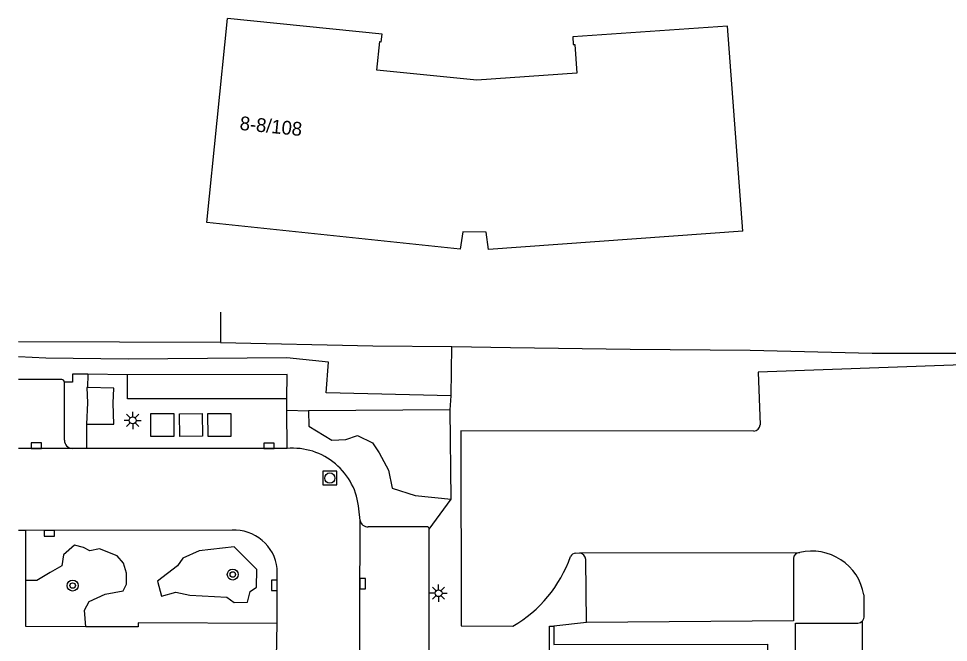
# Model space of a CAD drawing. Extents: x 132573 to 132944, y 398226 to 398676.
# Drawn here: x 132573 to 132640.6, y 398381.9 to 398427.3 of the extents above; entities that cross this region are included whole.
import ezdxf

# ---------------------------------------------------------------- set-up
doc = ezdxf.new("R2010")
doc.units = 0
for name, color, linetype in [('gg-afsc-hekwerk', 7, 'Continuous'), ('gg-anno-huisnummerreeks BGT', 7, 'Continuous'), ('gg-bbg-hoofdgebouw', 7, 'Continuous'), ('gg-bbg-lage trafo', 7, 'Continuous'), ('gg-knt-verharding', 7, 'Continuous'), ('gg-knt-verharding nz', 7, 'Continuous'), ('gg-kwrk-afval apart plaats', 7, 'Continuous'), ('gt-grn-groengrens', 7, 'Continuous'), ('gt-grn-vlakafsluiter', 7, 'Continuous'), ('gt-symb-boom', 7, 'Continuous'), ('gt-symb-kolk', 7, 'Continuous'), ('gt-symb-lichtmast', 7, 'Continuous'), ('gt-symb-rioolschacht', 7, 'Continuous')]:
    doc.layers.add(name, color=color, linetype=linetype)

msp = doc.modelspace()

# ---------------------------------------------------------------- linework, layer by layer
at = {"layer": 'gg-afsc-hekwerk'}
for p, q in [((132587.691, 398405.939), (132587.704, 398403.725)), ((132587.704, 398403.725), (132573.021, 398403.764))]:
    msp.add_line(p, q, dxfattribs=at)
for points in [[(132587.704, 398403.725), (132598.78, 398403.494), (132604.511, 398403.424)], [(132604.511, 398403.424), (132608.788, 398403.371), (132617.481, 398403.23), (132626.206, 398403.178), (132635.061, 398402.95), (132641.245, 398402.951), (132661.988, 398402.675), (132670.216, 398402.551), (132684.626, 398402.413)]]:
    msp.add_lwpolyline(points, dxfattribs=at)
at = {"layer": 'gg-bbg-hoofdgebouw'}
for p, q in [((132611.557, 398312.941), (132611.606, 398383.108)), ((132611.606, 398383.108), (132611.918, 398383.098))]:
    msp.add_line(p, q, dxfattribs=at)
for points in [[(132625.661, 398411.824), (132607.176, 398410.488), (132607.015, 398411.737), (132605.316, 398411.777), (132605.125, 398410.51), (132586.702, 398412.435), (132588.218, 398427.268)], [(132625.661, 398411.824), (132624.561, 398426.725), (132613.308, 398425.936), (132613.347, 398425.377), (132613.457, 398425.385), (132613.603, 398423.3), (132606.339, 398422.781), (132599.066, 398423.519), (132599.276, 398425.599), (132599.386, 398425.588), (132599.441, 398426.135), (132588.218, 398427.268)], [(132611.918, 398383.098), (132611.926, 398381.783), (132627.465, 398381.808), (132627.459, 398367.583), (132627.387, 398367.583), (132627.398, 398314.148)]]:
    msp.add_lwpolyline(points, dxfattribs=at)
at = {"layer": 'gg-bbg-lage trafo'}
for points in [[(132578.027, 398400.446), (132577.984, 398400.447), (132578.02, 398399.335), (132577.953, 398397.788)], [(132577.953, 398397.788), (132579.956, 398397.777), (132579.903, 398399.318), (132579.955, 398400.403), (132578.027, 398400.446)]]:
    msp.add_lwpolyline(points, dxfattribs=at)
at = {"layer": 'gg-knt-verharding'}
for p, q in [((132578.048, 398401.413), (132578.027, 398400.446)), ((132580.946, 398401.383), (132578.048, 398401.413)), ((132576.158, 398401.04), (132573.021, 398401.039)), ((132576.351, 398396.615), (132576.352, 398400.846)), ((132592.526, 398398.817), (132592.531, 398399.625)), ((132592.535, 398396.022), (132592.526, 398398.817)), ((132577.953, 398397.788), (132577.953, 398396.015)), ((132577.953, 398396.015), (132576.907, 398396.016)), ((132597.845, 398390.796), (132597.755, 398391.624)), ((132602.686, 398390.334), (132598.438, 398390.328)), ((132573.55, 398390.052), (132573.021, 398390.051)), ((132573.546, 398386.427), (132573.55, 398390.052)), ((132588.541, 398390.078), (132573.55, 398390.052)), ((132602.886, 398325.225), (132602.874, 398390.164)), ((132613.536, 398388.42), (132613.808, 398388.425)), ((132613.808, 398388.425), (132629.803, 398388.459)), ((132629.803, 398388.459), (132629.807, 398388.459)), ((132614.295, 398383.378), (132614.258, 398387.955)), ((132591.822, 398383.309), (132591.815, 398387.305)), ((132591.774, 398380.797), (132591.822, 398383.309)), ((132634.355, 398373.168), (132634.362, 398383.497))]:
    msp.add_line(p, q, dxfattribs=at)
for points in [[(132645.674, 398402.24), (132626.792, 398401.58), (132626.926, 398397.736)], [(132592.531, 398399.625), (132580.949, 398399.629), (132580.946, 398401.383)], [(132626.472, 398397.27), (132605.161, 398397.294), (132605.19, 398383.135), (132608.954, 398383.112)], [(132592.535, 398396.022), (132591.233, 398396.011), (132577.953, 398396.015)], [(132629.347, 398388.014), (132629.341, 398383.498), (132614.295, 398383.378)], [(132577.901, 398383.068), (132573.543, 398383.08), (132573.546, 398386.427)], [(132634.467, 398385.388), (132634.471, 398383.784), (132634.441, 398383.631), (132634.362, 398383.497)], [(132591.822, 398383.309), (132581.707, 398383.338), (132581.706, 398383.054), (132577.901, 398383.068)], [(132634.001, 398373.324), (132629.494, 398373.344), (132629.497, 398383.328), (132634.028, 398383.333), (132634.212, 398383.38), (132634.362, 398383.497)]]:
    msp.add_lwpolyline(points, dxfattribs=at)
for centre, radius, start, end in [((132576.144, 398400.832), 0.208, 3.75762, 86.24238), ((132626.422, 398397.772), 0.505, 275.63046, 355.86413), ((132576.956, 398396.619), 0.605, 180.39874, 265.33705), ((132592.948, 398391.215), 4.825, 49.8917, 94.90614), ((132592.949, 398391.216), 4.823, 4.8542, 49.89874), ((132598.417, 398390.911), 0.584, 191.39186, 272.04662), ((132602.695, 398390.155), 0.179, 2.88914, 92.8676), ((132588.705, 398386.952), 3.131, 49.74849, 93.00478), ((132588.706, 398386.953), 3.129, 6.45692, 49.73771), ((132613.554, 398387.95), 0.47, 92.18037, 153.74765), ((132613.743, 398387.913), 0.517, 4.71286, 82.79641), ((132629.806, 398388), 0.459, 90.40234, 178.19872), ((132630.694, 398384.735), 3.829, 9.82707, 103.40213), ((132604.284, 398391.232), 9.367, 299.90714, 340.84453)]:
    msp.add_arc(centre, radius, start, end, dxfattribs=at)
at = {"layer": 'gg-knt-verharding nz'}
for points in [[(132576.907, 398396.016), (132574.303, 398396.025), (132573.021, 398396.025)], [(132597.785, 398324.487), (132597.792, 398326.07), (132597.768, 398341.148), (132597.78, 398355.563), (132597.776, 398371.059), (132597.845, 398390.796)]]:
    msp.add_lwpolyline(points, dxfattribs=at)
at = {"layer": 'gg-kwrk-afval apart plaats'}
for points in [[(132584.309, 398396.896), (132582.639, 398396.884), (132582.633, 398398.553), (132584.303, 398398.565), (132584.309, 398396.896)], [(132586.37, 398398.565), (132586.381, 398396.907), (132584.73, 398396.89), (132584.719, 398398.548), (132586.37, 398398.565)], [(132588.448, 398398.553), (132588.456, 398396.901), (132586.794, 398396.903), (132586.786, 398398.555), (132588.448, 398398.553)]]:
    msp.add_lwpolyline(points, dxfattribs=at)
at = {"layer": 'gt-grn-groengrens'}
for p, q in [((132604.387, 398398.836), (132604.468, 398399.855)), ((132592.526, 398398.817), (132594.101, 398398.749)), ((132604.387, 398398.836), (132594.101, 398398.749)), ((132604.469, 398392.329), (132604.387, 398398.836))]:
    msp.add_line(p, q, dxfattribs=at)
for points in [[(132604.468, 398399.855), (132595.373, 398400.057), (132595.538, 398402.286), (132592.517, 398402.604), (132580.975, 398402.502), (132574.993, 398402.589), (132573.021, 398402.685)], [(132578.048, 398401.413), (132576.941, 398401.43), (132576.946, 398400.842), (132576.352, 398400.846)], [(132592.531, 398399.625), (132592.556, 398401.402), (132580.946, 398401.383)], [(132594.101, 398398.749), (132594.117, 398397.634), (132595.801, 398396.636), (132596.808, 398396.667), (132597.653, 398396.97), (132598.746, 398396.424), (132599.236, 398395.698), (132599.91, 398394.434), (132600.166, 398393.128), (132601.857, 398392.593), (132604.469, 398392.329)], [(132577.901, 398383.068), (132577.812, 398384.271), (132578.141, 398384.903), (132579.31, 398385.429), (132580.631, 398385.679), (132580.871, 398386.157), (132580.871, 398386.969), (132580.64, 398387.687), (132580.192, 398388.22), (132578.894, 398388.723), (132578.188, 398388.576), (132577.747, 398388.831), (132577.077, 398388.988), (132576.296, 398388.299), (132576.168, 398387.489), (132575.328, 398387.006), (132574.342, 398386.426), (132573.546, 398386.427)], [(132586.158, 398388.584), (132584.949, 398388.058), (132584.563, 398387.501), (132583.117, 398386.369), (132583.42, 398385.283), (132584.452, 398385.575), (132585.471, 398385.361), (132588.16, 398385.213), (132588.703, 398384.833), (132589.651, 398384.848), (132589.861, 398385.626), (132590.307, 398385.947), (132590.332, 398387.216), (132588.691, 398388.861), (132586.158, 398388.584)]]:
    msp.add_lwpolyline(points, dxfattribs=at)
at = {"layer": 'gt-grn-vlakafsluiter'}
for p, q in [((132604.468, 398399.855), (132604.511, 398403.424)), ((132602.874, 398390.164), (132604.469, 398392.329)), ((132614.295, 398383.378), (132611.918, 398383.098))]:
    msp.add_line(p, q, dxfattribs=at)
at = {"layer": 'gt-symb-boom'}
for centre, radius in [((132588.589, 398386.86), 0.4), ((132588.589, 398386.86), 0.2), ((132576.949, 398386.058), 0.4), ((132576.949, 398386.058), 0.2)]:
    msp.add_circle(centre, radius, dxfattribs=at)
at = {"layer": 'gt-symb-kolk'}
for points in [[(132574.303, 398396.025), (132574.678, 398396.025), (132574.678, 398396.425), (132573.928, 398396.425), (132573.928, 398396.025), (132574.303, 398396.025)], [(132591.233, 398396.011), (132591.608, 398396.012), (132591.607, 398396.412), (132590.857, 398396.41), (132590.858, 398396.01), (132591.233, 398396.011)], [(132575.263, 398390.053), (132574.888, 398390.053), (132574.888, 398389.653), (132575.638, 398389.653), (132575.638, 398390.053), (132575.263, 398390.053)], [(132591.815, 398386.078), (132591.815, 398386.453), (132591.415, 398386.453), (132591.415, 398385.703), (132591.815, 398385.703), (132591.815, 398386.078)], [(132597.833, 398386.187), (132597.832, 398385.812), (132598.232, 398385.81), (132598.234, 398386.56), (132597.834, 398386.562), (132597.833, 398386.187)]]:
    msp.add_lwpolyline(points, dxfattribs=at)
at = {"layer": 'gt-symb-lichtmast'}
for p, q in [((132581.137, 398398.239), (132580.872, 398398.504)), ((132581.314, 398398.312), (132581.314, 398398.687)), ((132581.491, 398398.239), (132581.756, 398398.504)), ((132581.064, 398398.062), (132580.689, 398398.062)), ((132581.137, 398397.885), (132580.872, 398397.62)), ((132581.314, 398397.812), (132581.314, 398397.437)), ((132581.756, 398397.62), (132581.491, 398397.885)), ((132581.564, 398398.062), (132581.939, 398398.062)), ((132603.373, 398385.677), (132603.108, 398385.942)), ((132603.55, 398385.75), (132603.55, 398386.125)), ((132603.727, 398385.677), (132603.992, 398385.942)), ((132603.3, 398385.5), (132602.925, 398385.5)), ((132603.373, 398385.323), (132603.108, 398385.058)), ((132603.55, 398385.25), (132603.55, 398384.875)), ((132603.992, 398385.058), (132603.727, 398385.323)), ((132603.8, 398385.5), (132604.175, 398385.5))]:
    msp.add_line(p, q, dxfattribs=at)
for centre in [(132581.314, 398398.062), (132603.55, 398385.5)]:
    msp.add_circle(centre, 0.25, dxfattribs=at)
at = {"layer": 'gt-symb-rioolschacht'}
msp.add_lwpolyline([(132595.146, 398393.371), (132596.146, 398393.371), (132596.146, 398394.371), (132595.146, 398394.371)], close=True, dxfattribs=at)
msp.add_circle((132595.646, 398393.871), 0.375, dxfattribs=at)

# ---------------------------------------------------------------- texts
at = {"layer": 'gg-anno-huisnummerreeks BGT'}
msp.add_text('8-8/108', height=1, rotation=354.2, dxfattribs=at).set_placement((132589.063, 398419.184))

doc.saveas('drawing.dxf')
